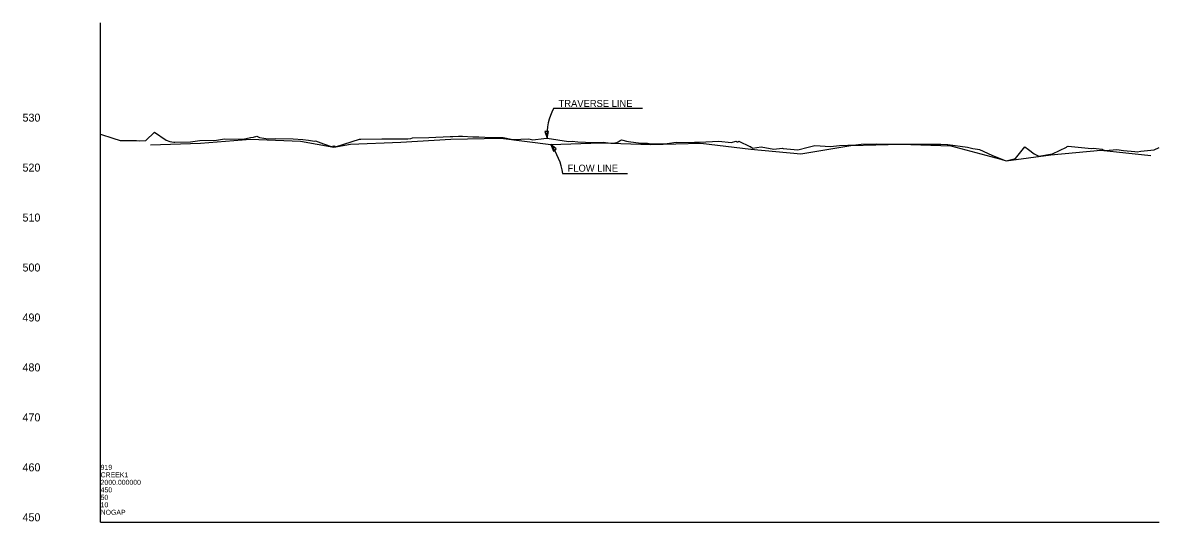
# Model space of a CAD drawing. Extents: x 49922 to 54713, y 49991 to 62800.
# Drawn here: x 49922 to 51059, y 53000 to 53500 of the extents above; entities that cross this region are included whole.
import ezdxf

# ---------------------------------------------------------------- set-up
doc = ezdxf.new("R2010")
doc.units = 0
for name, color, linetype in [('RD_DDB_ElevTX', 7, 'Continuous'), ('RD_DDB_Profile_EX', 7, 'Continuous'), ('RD_GPK_Profile_Cell', 7, 'Continuous'), ('RD_TX_Profile', 7, 'Continuous')]:
    doc.layers.add(name, color=color, linetype=linetype)

msp = doc.modelspace()

# ---------------------------------------------------------------- linework, layer by layer
at = {"layer": 'RD_DDB_Profile_EX'}
for points in [[(50000, 53388.6), (50012.2, 53384.3), (50019.6, 53382.2), (50020.8, 53382), (50036, 53382.2), (50038.4, 53381.8), (50045.2, 53382.2), (50053.9, 53390.4), (50065.5, 53382.5), (50069.3, 53381.2), (50073.3, 53380.3), (50074.3, 53380.4), (50089.9, 53380.9), (50099.1, 53382.1), (50115.7, 53382.6), (50124, 53383.7), (50138, 53383.5), (50142.5, 53383.6), (50149.9, 53385.1), (50152.9, 53385.3), (50156.1, 53386.4), (50158.9, 53385.1), (50167.5, 53383.7), (50174.9, 53384), (50192.5, 53383.7), (50202.1, 53383.2), (50207.7, 53382.4), (50213.8, 53381.6), (50214.8, 53381.8), (50223, 53378.8), (50231.6, 53375.9), (50232, 53376.4), (50233.2, 53376.9), (50234.1, 53376.4), (50234.7, 53375.9), (50258.9, 53383.6), (50259.4, 53383.6), (50260.2, 53383.6), (50281.2, 53383.7), (50285.1, 53383.9), (50307.2, 53383.9), (50310, 53384), (50311.7, 53384.7), (50328, 53385.2), (50349.5, 53386.2), (50352, 53386.1), (50357.7, 53386.5), (50359.6, 53386.6), (50361.7, 53386.5), (50372, 53385.7), (50378.2, 53385.7), (50390.6, 53385.1), (50402.6, 53385.1), (50412.1, 53383), (50428.1, 53383.8), (50432.3, 53382.9), (50443.1, 53384), (50446.4, 53384.4), (50467.9, 53381.1), (50471.4, 53381.6), (50477.1, 53380.9), (50492.4, 53380), (50502.5, 53380.3), (50507.6, 53379.7), (50511.4, 53379.5), (50514, 53379.9), (50516.3, 53380.2), (50517.4, 53380.7), (50519.6, 53382.2), (50520.8, 53382.9), (50522.3, 53382.6), (50525.8, 53381.4), (50527.8, 53381), (50540, 53379.3), (50546.9, 53379.5), (50550.6, 53378.9), (50566.6, 53379.2), (50575.5, 53380.6), (50590.9, 53380.2), (50593.7, 53380.5), (50598.7, 53380.3), (50618.2, 53381.5), (50630.4, 53380.2), (50635.5, 53381.6), (50636.6, 53380.9), (50637.5, 53380.9), (50638, 53381.4), (50649.2, 53376.2), (50649.7, 53376), (50651.9, 53374.3), (50660.4, 53375.8), (50673.1, 53373.3), (50681.3, 53374.5), (50682.6, 53374.2), (50697.2, 53372.9), (50707.5, 53375.5), (50714, 53377.1), (50729.8, 53376.2), (50738.7, 53377.2), (50755.1, 53377.7), (50760.4, 53378.3)], [(50050, 53377.8), (50100, 53379.3), (50150, 53383.4), (50200, 53381.5), (50233.1, 53375.5), (50250, 53378.4), (50300, 53380.6), (50350, 53383.5), (50400, 53384.3), (50450, 53378), (50500, 53379.9), (50550, 53378.1), (50600, 53379.3), (50650, 53373.3), (50700, 53368.8), (50750, 53377), (50800, 53378.4), (50850, 53376.9), (50900, 53363.4), (50905.3, 53361.7), (50950, 53367.9), (51000, 53372.6), (51050, 53367.1)], [(50760.4, 53378.3), (50775.3, 53378.7), (50779.1, 53378.5), (50800.2, 53378.5), (50804.9, 53378.3), (50825.2, 53378.3), (50840.2, 53378.3), (50846.3, 53378.1), (50847, 53378), (50866.8, 53375.3), (50872, 53374.1), (50876.6, 53373.5), (50878.7, 53373), (50891.1, 53367.5), (50903.5, 53362.4), (50905.3, 53361.7), (50914.7, 53364.2), (50924, 53375.8), (50927.9, 53373.2), (50933.3, 53368.6), (50938, 53366.3), (50951.6, 53368.9), (50965.9, 53375.6), (50966.3, 53376.1), (50967.3, 53376.3), (50990.9, 53374.1), (50992.4, 53374.3), (51001.4, 53373.6), (51002.4, 53372.7), (51004.6, 53372.1), (51016, 53373.2), (51022.7, 53372.1), (51034.1, 53371), (51036.4, 53370.8), (51040.1, 53371.3), (51053.4, 53372.8), (51058.5, 53375)]]:
    msp.add_lwpolyline(points, dxfattribs=at)
at = {"layer": 'RD_GPK_Profile_Cell'}
for q in [(50000, 53500), (51058.5, 53000), (50000, 53000)]:
    msp.add_line((50000, 53000), q, dxfattribs=at)
at = {"layer": 'RD_TX_Profile'}
for p, q in [((50541.7, 53414.2), (50452.9, 53414.2)), ((50526.8, 53348.9), (50461.9, 53348.9))]:
    msp.add_line(p, q, dxfattribs=at)
for points in [[(50444.2, 53391), (50446.4, 53384.4), (50447.8, 53391.2)], [(50455.5, 53373.7), (50450, 53378), (50452.7, 53371.5)]]:
    msp.add_lwpolyline(points, close=True, dxfattribs=at)
for centre, radius, start, end in [((50503.5, 53387.5), 57.2, 152.2683, 183.1759), ((50401.6, 53341.1), 60.9, 7.3924, 37.2765)]:
    msp.add_arc(centre, radius, start, end, dxfattribs=at)

# ---------------------------------------------------------------- texts
at = {"layer": 'RD_DDB_ElevTX'}
for s, p in [('530', (49921.9, 53401)), ('520', (49921.9, 53351)), ('510', (49921.9, 53301)), ('500', (49921.9, 53251)), ('490', (49921.9, 53201)), ('480', (49921.9, 53151)), ('470', (49921.9, 53101)), ('460', (49921.9, 53051)), ('450', (49921.9, 53001))]:
    msp.add_text(s, height=8, dxfattribs=at).set_placement(p)
at = {"layer": 'RD_GPK_Profile_Cell'}
for s, p in [('919', (50000, 53052.5)), ('CREEK1', (50000, 53045)), ('2000.000000', (50000, 53037.5)), ('450', (50000, 53030)), ('50', (50000, 53022.5)), ('10', (50000, 53015)), ('NOGAP', (50000, 53007.5))]:
    msp.add_text(s, height=5, dxfattribs=at).set_placement(p)
at = {"layer": 'RD_TX_Profile'}
for s, p in [('TRAVERSE LINE', (50457.9, 53415.7)), ('FLOW LINE', (50466.9, 53350.9))]:
    msp.add_text(s, height=7, dxfattribs=at).set_placement(p)

doc.saveas('drawing.dxf')
